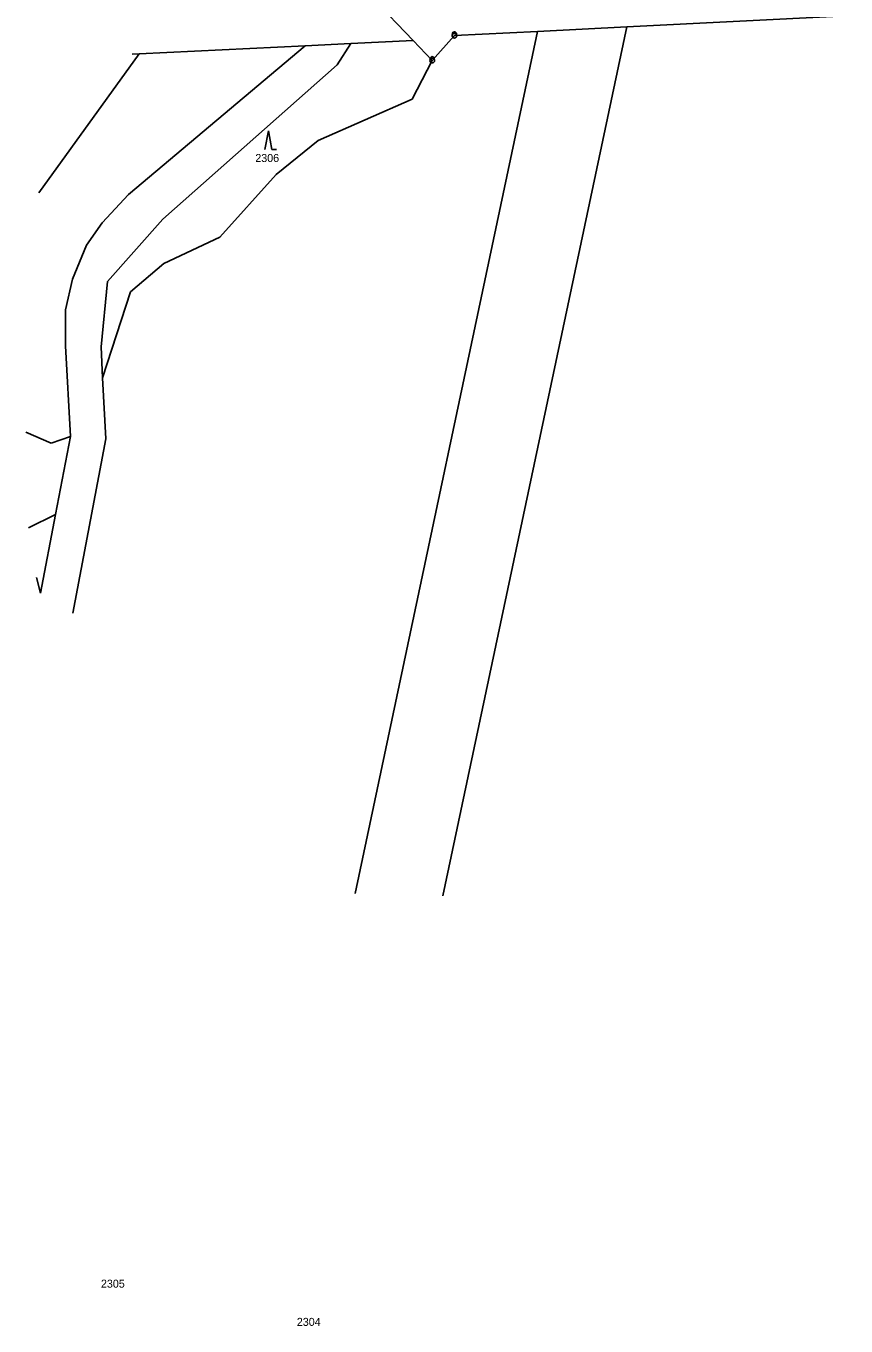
# Model space of a CAD drawing. Extents: x -801826 to -800592, y -1032871 to -1031813.
# Drawn here: x -801825.2 to -801651, y -1032792.2 to -1032516 of the extents above; entities that cross this region are included whole.
import ezdxf

# ---------------------------------------------------------------- set-up
doc = ezdxf.new("R2010")
doc.units = 0
for name, color, linetype in [('Vrstva 1', 7, 'Continuous'), ('Vrstva 18', 7, 'Continuous'), ('Vrstva 24', 7, 'Continuous'), ('Vrstva 25', 7, 'Continuous')]:
    doc.layers.add(name, color=color, linetype=linetype)

msp = doc.modelspace()

# ---------------------------------------------------------------- linework, layer by layer
at = {"layer": 'Vrstva 1'}
for p, q in [((-801751.51, -1032510.07), (-801742.91, -1032519.09)), ((-801697.53, -1032516.2), (-801650.95, -1032513.86)), ((-801755.28, -1032700.26), (-801716.53, -1032517.15)), ((-801738.87, -1032523.32), (-801734.17, -1032518.04)), ((-801697.53, -1032516.2), (-801736.6, -1032700.77)), ((-801734.17, -1032518.04), (-801716.53, -1032517.15)), ((-801716.53, -1032517.15), (-801697.53, -1032516.2)), ((-801765.86, -1032520.2), (-801803.44, -1032551.79)), ((-801801.19, -1032521.9), (-801765.86, -1032520.2)), ((-801765.86, -1032520.2), (-801756.17, -1032519.73)), ((-801759.07, -1032524.22), (-801756.17, -1032519.73)), ((-801756.17, -1032519.73), (-801742.91, -1032519.09)), ((-801742.91, -1032519.09), (-801738.87, -1032523.32)), ((-801801.19, -1032521.9), (-801822.48, -1032551.43)), ((-801802.62, -1032521.97), (-801801.19, -1032521.9)), ((-801743.13, -1032531.54), (-801738.87, -1032523.32)), ((-801796.1, -1032557.03), (-801759.07, -1032524.22)), ((-801763.11, -1032540.34), (-801743.13, -1032531.54)), ((-801772.02, -1032547.55), (-801763.11, -1032540.34)), ((-801784.02, -1032560.84), (-801772.02, -1032547.55)), ((-801803.44, -1032551.79), (-801809.01, -1032557.84)), ((-801807.89, -1032570.28), (-801796.1, -1032557.03)), ((-801809.01, -1032557.84), (-801812.37, -1032562.57)), ((-801812.37, -1032562.57), (-801815.3, -1032569.78)), ((-801795.92, -1032566.44), (-801784.02, -1032560.84)), ((-801803.03, -1032572.45), (-801795.92, -1032566.44)), ((-801815.3, -1032569.78), (-801816.78, -1032576.32)), ((-801809.26, -1032584.15), (-801807.89, -1032570.28)), ((-801808.92, -1032590.74), (-801803.03, -1032572.45)), ((-801816.78, -1032576.32), (-801816.78, -1032583.96)), ((-801816.78, -1032583.96), (-801815.78, -1032603.2)), ((-801808.92, -1032590.74), (-801809.26, -1032584.15)), ((-801808.25, -1032603.71), (-801808.92, -1032590.74)), ((-801825.21, -1032602.27), (-801819.88, -1032604.59)), ((-801819.88, -1032604.59), (-801815.78, -1032603.2)), ((-801815.78, -1032603.2), (-801818.94, -1032619.8)), ((-801815.27, -1032640.7), (-801808.25, -1032603.71)), ((-801818.94, -1032619.8), (-801824.7, -1032622.57)), ((-801818.94, -1032619.8), (-801822.11, -1032636.46)), ((-801822.95, -1032633.13), (-801822.11, -1032636.46))]:
    msp.add_line(p, q, dxfattribs=at)
at = {"layer": 'Vrstva 24'}
for centre, radius in [((-801734.17, -1032518.04), 0.5), ((-801734.17, -1032518.04), 0.0364), ((-801738.87, -1032523.32), 0.5), ((-801738.87, -1032523.32), 0.0364)]:
    msp.add_circle(centre, radius, dxfattribs=at)
for centre in [(-801734.17, -1032517.67), (-801738.87, -1032522.95)]:
    msp.add_arc(centre, 0.45, 344.4473, 196.3778, dxfattribs=at)
at = {"layer": 'Vrstva 25'}
for p, q in [((-801773.69, -1032538.25), (-801774.43, -1032542.25)), ((-801773.69, -1032538.25), (-801772.96, -1032542.25)), ((-801772.96, -1032542.25), (-801771.96, -1032542.25))]:
    msp.add_line(p, q, dxfattribs=at)

# ---------------------------------------------------------------- texts
at = {"layer": 'Vrstva 18'}
for s, p in [('2306', (-801776.48, -1032544.88)), ('2305', (-801809.28, -1032784.02)), ('2304', (-801767.65, -1032792.14))]:
    msp.add_text(s, height=1.7, dxfattribs=at).set_placement(p)

doc.saveas('drawing.dxf')
